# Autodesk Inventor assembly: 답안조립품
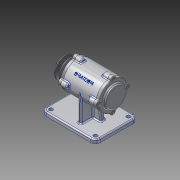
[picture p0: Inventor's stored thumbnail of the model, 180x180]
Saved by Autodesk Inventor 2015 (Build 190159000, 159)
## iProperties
Created: 2015-12
Part Number: 답안조립품
Document SubType Name: Assembly
Designer: 601-23
Author: 601-23
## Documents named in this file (11)
- C:\Users\601-23\Desktop\451208V1009\답안조립품.iam
- C:\Users\601-23\Desktop\451208V1009\본체.ipt
- C:\Users\601-23\Desktop\451208V1009\축.ipt
- C:\Users\601-23\Desktop\451208V1009\베어링 6204.ipt
- C:\Users\601-23\Desktop\451208V1009\커버2.ipt
- C:\Users\601-23\Desktop\451208V1009\커버.ipt
- C:\Users\601-23\Desktop\451208V1009\오일실.ipt
- C:\Users\601-23\Desktop\451208V1009\키(4 x 4 x 12).ipt
- C:\Users\601-23\Desktop\451208V1009\V-벨트풀리.ipt
- C:\Users\601-23\Desktop\451208V1009\너트 M12x1.25.ipt
- C:\Users\601-23\Desktop\451208V1009\볼트 M4 x 12.ipt
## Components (6 placed, 5 different names)
1. KS B 2023 6204 - 20 x 47 x 14:1
2. KS B 2023 6204 - 20 x 47 x 14:2
3. KS B 2804 D D - 20 32 8:1
4. KS B 1311 (I) 4 x 4 x 12:1 — 각도:1
5. V-벨트풀리:1
6. KS B 1012 클래스 1 일반 - 미터 M12x1.25:1 — 각도:1
## Component patterns: 구성요소 패턴 1:2 (4 elements), 구성요소 패턴 1:3 (4 elements), 구성요소 패턴 1:4 (4 elements)
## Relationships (1: Angle 1)
- 각도:1 [Angle]: KS B 1311 (I) 4 x 4 x 12:1 ↔ KS B 1012 클래스 1 일반 - 미터 M12x1.25:1
